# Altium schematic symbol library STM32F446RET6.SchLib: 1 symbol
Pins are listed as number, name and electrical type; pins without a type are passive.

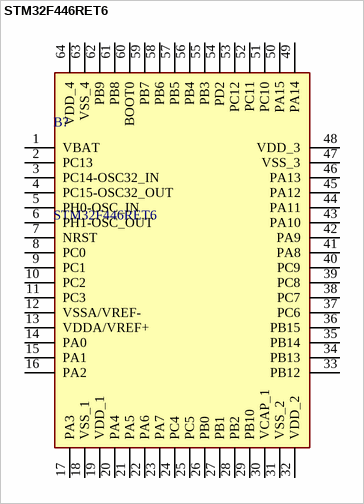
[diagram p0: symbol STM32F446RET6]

## STM32F446RET6
designator B?
32-Bit MCU+DSP 512K Flash 180MHz LQFP64 STMicroelectronics STM32F446RET6, 32bit ARM Cortex M4 MCU, 180MHz, 512 kB Flash, 64-Pin LQFP; Geometry.Height: 1.6mm
footprint QFP50P1200X1200X160-64N
pins: 1 VBAT, 2 PC13, 3 PC14-OSC32_IN, 4 PC15-OSC32_OUT, 5 PH0-OSC_IN, 6 PH1-OSC_OUT, 7 NRST, 8 PC0, 9 PC1, 10 PC2, 11 PC3, 12 VSSA/VREF-, 13 VDDA/VREF+, 14 PA0, 15 PA1, 16 PA2, 17 PA3, 18 VSS_1, 19 VDD_1, 20 PA4, 21 PA5, 22 PA6, 23 PA7, 24 PC4, 25 PC5, 26 PB0, 27 PB1, 28 PB2, 29 PB10, 30 VCAP_1, 31 VSS_2, 32 VDD_2, 33 PB12, 34 PB13, 35 PB14, 36 PB15, 37 PC6, 38 PC7, 39 PC8, 40 PC9, 41 PA8, 42 PA9, 43 PA10, 44 PA11, 45 PA12, 46 PA13, 47 VSS_3, 48 VDD_3, 49 PA14, 50 PA15, 51 PC10, 52 PC11, 53 PC12, 54 PD2, 55 PB3, 56 PB4, 57 PB5, 58 PB6, 59 PB7, 60 BOOT0, 61 PB8, 62 PB9, 63 VSS_4, 64 VDD_4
